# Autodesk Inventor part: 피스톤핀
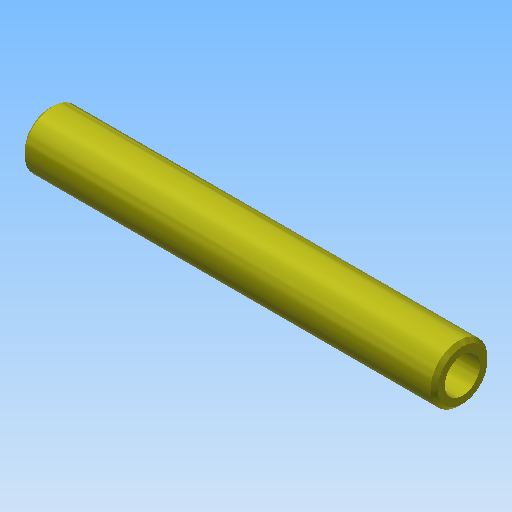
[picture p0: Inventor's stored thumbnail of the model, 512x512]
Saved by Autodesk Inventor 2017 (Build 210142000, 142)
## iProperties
Created: 2016-11
Part Number: 피스톤핀
Material: 강철, 탄소
Document SubType Name: Modeling
Designer: mduedu
Density: 7.87 g/cm^3
Mass: 13.9342 g
Surface Area: 24.1465 cm^2
Volume: 1.77055 cm^3
Appearance: 노란색
Author: mduedu
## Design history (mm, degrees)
sketch "스케치1"
  geometry: C1 r 2.5 at (0, 0); C2 r 4 at (0, 0); 1 further point
  constraints: 2 centre point, 2 coincident
  dimensions: "d0" = 5 diameter of C1; "d1" = 8 diameter of C2
extrude "돌출1" new body sketch "스케치1" stored distance "d2" = 58; taper "d3" = 0 deg
chamfer "모따기1" distance "d4" = 0.5; stored, may be unused: second distance "d5" = 2, angle "d6" = 45 deg
node "솔리드1"
